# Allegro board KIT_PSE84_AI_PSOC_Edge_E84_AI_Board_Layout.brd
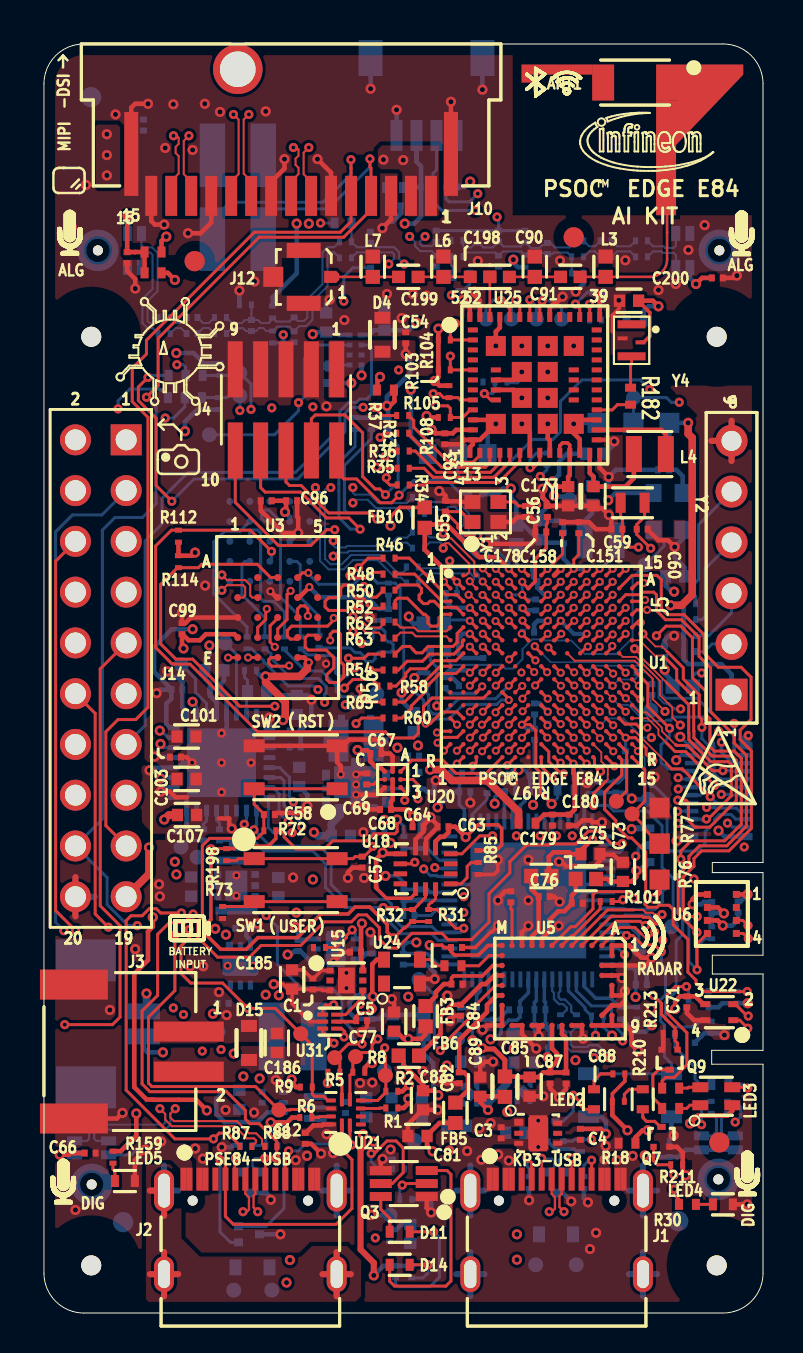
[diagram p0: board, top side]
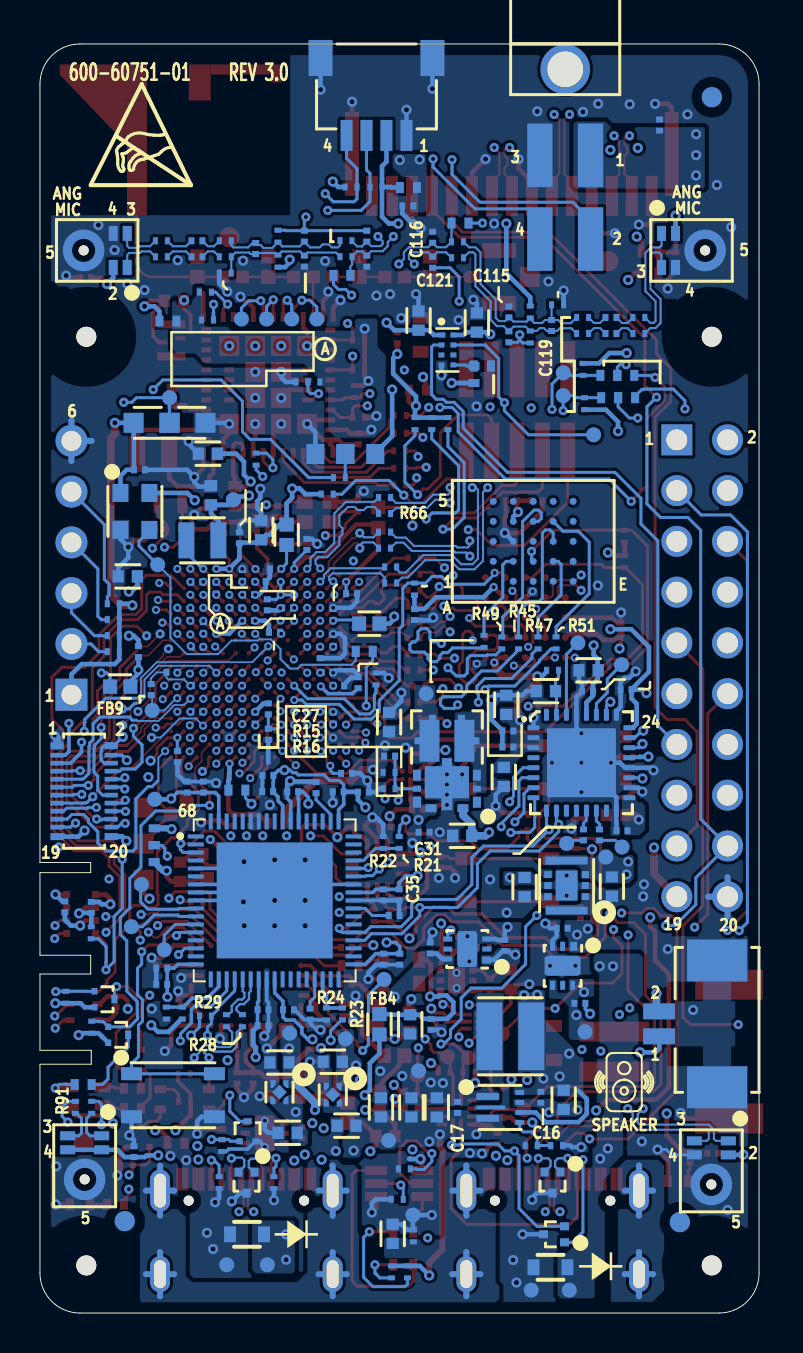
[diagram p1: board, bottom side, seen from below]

Outline 35.99 x 63.5 mm; copper layers: TOP, L02_GND, L03_SIG1, L04_SIG2, L05_PWR, BOTTOM. Coordinates in mm from the lower left corner of the outline.
Outline path: 0,61.5 arc(0.59,62.91) 2,63.5 33.99,63.5 arc(35.41,62.91) 35.99,61.5 35.99,22.54 33.45,22.54 33.45,22.03 35.99,22.03 35.99,17.9 33.45,17.9 33.45,16.96 35.99,16.96 35.99,13.14 33.43,13.14 33.43,12.45 35.99,12.45 35.99,2 arc(35.41,0.59) 33.99,0 2,0 arc(0.59,0.59) 0,2 0,61.5

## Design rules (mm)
constraint set DEFAULT: min track width 0.15
net group AMIC1_CTB_IN: nets AMIC1_CTB_INN AMIC1_CTB_INP
net group DP2: nets N17695662 N17695815
net group DP3: nets N17695725 N17695803
net group DP4: nets N17695749 N17695801
net group DP5: nets N17695747 N17695799
net group DP6: nets N17989965 N17989977
net group DP7: nets N17696044 N17696122
net group DP8: nets N17696068 N17696120
net group DP9: nets N17696066 N17696118
net group DP10: nets N17695981 N17696134
net group DP12: nets N17709188 N17709192
net group DP13: nets N17709220 N17709224
net group DP14: nets N17709256 N17709266
net group DSI_CLK: nets DSI_CLK_N DSI_CLK_P
net group DSI_DATA0: nets DSI_DATA0_N DSI_DATA0_P
net group DSI_DATA1: nets DSI_DATA1_N DSI_DATA1_P
net group KP_USB: nets N17581130 N17581131
net group P6_USB: nets PE84_USB_DM PE84_USB_DP
net group WL_SDIO_CMD: nets N17708163 WL_SDIO_CMD
net group WL_SDIO_DATA0: nets N17708293 WL_SDIO_DATA0
net group WL_SDIO_DATA1: nets N17708259 WL_SDIO_DATA1
net group WL_SDIO_DATA2: nets N17708201 WL_SDIO_DATA2
net group WL_SDIO_DATA3: nets N17708171 WL_SDIO_DATA3
net group I2S: nets I2S_TX_FSYNC I2S_TX_MCK I2S_TX_SCK I2S_TX_SD
net group POWER: nets AMIC_1V8 DISP_VDD_3V3 MCU_VDD_3V3 N17462113 N17691977 N17691999 N17694386 N17694402 N17699019 N17699478 N17701248 N17701356 N17701674 N17701786 N17713209 P5LP_VCCD P5LP_VDD PE84_VBUS PE84_VCCD PE84_VDDA USB_V_SENSE VBAT_IN VDD_5V VDDA_RADAR VDDD_RADAR VDDIO_RADIO VDDLF_RADAR VDDPLL_RADAR VDDRF_RADAR VDDVCO_RADAR VTARG_MEAS
net group RF: nets N17920449 N17920453 N17920674 N17920680 RF_OUT
net group SMIF0: nets N17708861 N17708893 N17708925 N17708957 N17709105
net group SMIF0_DATA: nets SMIF0_CLKP SMIF0_DATA0 SMIF0_DATA1 SMIF0_DATA2 SMIF0_DATA3
net group SMIF1: nets N17708863 N17708895 N17708927 N17708959 N17708991 N17709023 N17709055 N17709075 N17709107 N17709123 N17709155
net group SMIF1_DATA: nets SMIF1_CLKN SMIF1_CLKP SMIF1_DATA0 SMIF1_DATA1 SMIF1_DATA2 SMIF1_DATA3 SMIF1_DATA4 SMIF1_DATA5 SMIF1_DATA6 SMIF1_DATA7 SMIF1_RWDS

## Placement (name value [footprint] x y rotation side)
ANT1  2450AD18A6050  [ANTENNA_2450AD18A6050]  29.59 61.57 0 top
C1  0.1uF  [CAPC0603_0201N]  13.46 16.46 90 top
C3  0.1uF  [CAPC0603_0201N]  22.89 9.02 90 top
C4  0.1uF  [CAPC0603_0201N]  26.85 8.94 270 top
C5  0.1uF  [CAPC0603_0201N]  15.9 14.63 180 top
C6  0.1uF  [CAPC0603_0201N]  15.6 18.06 0 top
C7  0.1uF  [CAPC0603_0201N]  9.86 19.25 180 bottom
C8  0.1uF  [CAPC0603_0201N]  12.73 18.39 270 bottom
C9  0.1uF  [CAPC0603_0201N]  8.97 15.5 0 bottom
C11  0.1uF  [CAPC0603_0201N]  16.46 18.26 270 bottom
C12  0.1uF  [CAPC0603_0201N]  13.08 8.74 270 top
C13  10nF  [CAPC1005_0402N]  18.34 3.96 90 bottom
C14  22uF  [CAPC1005_0402N]  9.78 10.67 270 bottom
C16  0.1uF  [CAPC0603_0201N]  10.92 10.8 270 bottom
C17  0.1uF  [CAPC0603_0201N]  15.09 10.29 90 bottom
C21  10uF  [CAPC1005_0402N]  11.74 21.31 90 bottom
C27  330PF  [CAPC0603_0201N]  18.49 27.86 180 bottom
C28  22uF  [CAPC1005_0402N]  18.52 29.57 90 bottom
C30  10uF  [CAPC1005_0402N]  14.86 23.88 0 bottom
C31  1uF  [CAPC0603_0201N]  16.77 24.05 180 bottom
C35  1uF  [CAPC0603_0201N]  18.02 20.92 270 bottom
C36  0.1uF  [CAPC0603_0201N]  18.82 20.92 270 bottom
C37  1uF  [CAPC0603_0201N]  17.98 17.7 270 bottom
C38  0.1uF  [CAPC0603_0201N]  18.8 17.7 270 bottom
C39  1uF  [CAPC0603_0201N]  24.83 14.38 180 bottom
C40  0.1uF  [CAPC0603_0201N]  24.83 15.18 180 bottom
C41  1uF  [CAPC0603_0201N]  29.9 16.45 0 bottom
C42  0.1uF  [CAPC0603_0201N]  29.9 17.26 0 bottom
C43  1uF  [CAPC0603_0201N]  22.18 26.29 90 bottom
C44  1uF  [CAPC0603_0201N]  23.55 15.17 180 bottom
C45  0.1uF  [CAPC0603_0201N]  23.34 26.09 0 bottom
C46  1uF  [CAPC0603_0201N]  21.07 26.07 0 bottom
C47  0.1uF  [CAPC0603_0201N]  19.8 26.06 180 bottom
C48  1uF  [CAPC0603_0201N]  24.59 26.9 0 bottom
C49  0.1uF  [CAPC0603_0201N]  24.6 26.09 0 bottom
C50  1uF  [CAPC0603_0201N]  27.81 26.32 90 bottom
C51  0.1uF  [CAPC0603_0201N]  28.63 26.32 90 bottom
C52  1uF  [CAPC0603_0201N]  18.26 19.89 180 bottom
C53  1uF  [CAPC0603_0201N]  22.47 14.95 270 bottom
C54  1uF  [CAPC0603_0201N]  18.11 48.79 90 top
C55  10pF  [CAPC0603_0201N]  20.09 40.37 90 top
C56  10pF  [CAPC0603_0201N]  24.11 40.11 270 top
C57  0.1uF  [CAPC0603_0201N]  15.93 22.56 270 top
C58  0.1uF  [CAPC0603_0201N]  11.28 24.94 0 top
C59  22pF  [CAPC0603_0201N]  28.68 39.22 0 top
C60  22pF  [CAPC0603_0201N]  29.95 39.22 180 top
C61  0.1uF  [CAPC0603_0201N]  31.01 42.19 180 bottom
C62  0.1uF  [CAPC0603_0201N]  34.75 20.32 90 bottom
C63  0.1uF  [CAPC0603_0201N]  19.98 24.33 0 top
C64  0.1uF  [CAPC0603_0201N]  18.73 24.33 0 top
C65  0.1uF  [CAPC0603_0201N]  33.43 20.3 270 bottom
C66  0.1uF  [CAPC0603_0201N]  2.31 8 0 top
C67  0.1uF  [CAPC0603_0201N]  16.61 27.99 0 top
C68  0.1uF  [CAPC0603_0201N]  17.1 25.2 180 top
C69  2.2uF  [CAPC0603_0201N]  16.16 26.72 90 top
C70  0.1uF  [CAPC0603_0201N]  31.29 8.08 90 bottom
C71  0.1uF  [CAPC0603_0201N]  32.18 15.57 270 top
C72  0.47uF  [CAPC0603_0201N]  23.37 20.83 270 top
C73  10uF  [CAPC1005_0402N]  28.98 22.07 90 top
C74  1uF  [CAPC0603_0201N]  26.7 20.5 0 top
C75  10uF  [CAPC1005_0402N]  27.36 22.96 0 top
C76  1uF  [CAPC0603_0201N]  25.04 20.83 0 top
C77  10uF  [CAPC1005_0402N]  17.53 14.58 90 top
C78  1uF  [CAPC0603_0201N]  20.68 16.46 0 top
C79  10uF  [CAPC1005_0402N]  17.46 14.44 270 bottom
C80  1uF  [CAPC0603_0201N]  16.42 14.44 270 bottom
C81  10uF  [CAPC1005_0402N]  18.7 8.86 180 top
C82  1uF  [CAPC0603_0201N]  20.79 11.77 270 top
C83  10uF  [CAPC1005_0402N]  18.98 10.64 270 top
C84  1uF  [CAPC0603_0201N]  20.85 15.15 270 top
C85  10uF  [CAPC1005_0402N]  24.31 11.32 270 top
C86  1uF  [CAPC0603_0201N]  20.65 18.29 0 top
C87  1uF  [CAPC0603_0201N]  25.33 11.76 270 top
C88  1uF  [CAPC0603_0201N]  26.13 11.76 270 top
C89  10uF  [CAPC1005_0402N]  21.84 11.32 90 top
C90  8.2pF  [CAPC1005_0402M]  22.81 51.84 0 top
C91  2.7pF  [CAPC1005_0402M]  26.35 51.84 0 top
C92  4.7uF  [CAPC1005_0402N]  27.51 40.87 270 top
C93  0.1uF  [CAPC0603_0201N]  20.07 43.74 270 top
C94  4.7uF  [CAPC1005_0402N]  27.59 43 0 bottom
C95  4.7uF  [CAPC1005_0402N]  26.24 40.87 270 top
C96  1uF  [CAPC0603_0201N]  12.4 40.64 0 top
C97  0.1uF  [CAPC0603_0201N]  11.13 40.64 180 top
C98  1uF  [CAPC0603_0201N]  17.25 34.95 270 bottom
C99  0.1uF  [CAPC0603_0201N]  6.91 34.24 90 top
C100  0.033uF  [CAPC1005_0402N]  10.67 31.12 0 bottom
C101  22uF  [CAPC1005_0402N]  7.14 28.85 0 top
C102  0.1uF  [CAPC0603_0201N]  6.65 31.19 0 bottom
C103  22uF  [CAPC1005_0402N]  7.14 26.72 0 top
C104  0.1uF  [CAPC0603_0201N]  6.58 27.81 0 top
C105  0.47uF  [CAPC0603_0201N]  8.79 23.93 90 bottom
C106  0.47uF  [CAPC0603_0201N]  7.99 23.93 90 bottom
C107  10uF  [CAPC1005_0402N]  7.16 24.92 0 top
C108  0.1uF  [CAPC0603_0201N]  6.86 24.13 0 bottom
C109  10uF  [CAPC1005_0402N]  8.53 32.16 0 bottom
C110  0.1uF  [CAPC0603_0201N]  8.59 31.12 0 bottom
C111  10uF  [CAPC1005_0402N]  12.65 30.43 90 bottom
C112  0.1uF  [CAPC0603_0201N]  12.57 29.12 0 bottom
C113  10uF  [CAPC1005_0402N]  12.78 26.82 270 bottom
C114  0.1uF  [CAPC0603_0201N]  12.57 28.32 0 bottom
C115  10pF  [CAPC0603_0201N]  12.52 50.09 90 bottom
C116  12pF  [CAPC0603_0201N]  16.34 53.82 90 bottom
C117  0.1uF  [CAPC0603_0201N]  7.41 49.81 0 bottom
C118  0.1uF  [CAPC0603_0201N]  4.17 52.81 270 top
C119  390pF  [CAPC0603_0201N]  10.38 49.41 270 bottom
C120  0.1uF  [CAPC0603_0201N]  7.41 49.01 0 bottom
C121  12pF  [CAPC0603_0201N]  16.34 52.57 90 bottom
C122  10pF  [CAPC0603_0201N]  12.52 48.85 90 bottom
C123  10pF  [CAPC0603_0201N]  22.76 52.63 270 bottom
C124  12pF  [CAPC0603_0201N]  19.64 52.63 270 bottom
C125  0.1uF  [CAPC0603_0201N]  28.14 52.85 180 bottom
C126  0.1uF  [CAPC0603_0201N]  33.71 51.79 0 top
C127  390pF  [CAPC0603_0201N]  25.2 53.26 90 bottom
C128  0.1uF  [CAPC0603_0201N]  28.14 53.65 180 bottom
C129  12pF  [CAPC0603_0201N]  19.64 53.88 270 bottom
C130  10pF  [CAPC0603_0201N]  22.76 53.88 270 bottom
C136  1uF  [CAPC0603_0201N]  17.58 55.4 0 bottom
C137  1uF  [CAPC0603_0201N]  24.97 36.6 180 bottom
C138  0.1uF  [CAPC0603_0201N]  26.01 38.79 90 bottom
C139  10uF  [CAPC1005_0402N]  31.6 36.86 0 bottom
C140  0.1uF  [CAPC0603_0201N]  26.19 35.28 180 bottom
C141  0.1uF  [CAPC0603_0201N]  27.18 36.27 270 bottom
C142  0.1uF  [CAPC0603_0201N]  24.26 34.06 0 bottom
C143  0.1uF  [CAPC0603_0201N]  24.21 37.24 0 bottom
C144  0.1uF  [CAPC0603_0201N]  26.52 28.45 90 bottom
C145  0.1uF  [CAPC0603_0201N]  21.97 33.05 270 bottom
C146  0.1uF  [CAPC0603_0201N]  31.06 33.1 90 bottom
C147  1uF  [CAPC0603_0201N]  28.12 31.4 0 bottom
C148  1uF  [CAPC0603_0201N]  28.12 33.33 0 bottom
C149  0.1uF  [CAPC0603_0201N]  29.39 32.06 0 bottom
C150  4.7uF  [CAPC1005_0402N]  24.92 39.17 90 bottom
C151  0.1uF  [CAPC0603_0201N]  26.77 39.29 90 top
C152  4.7uF  [CAPC1005_0402N]  27.43 40.92 90 bottom
C153  1uF  [CAPC0603_0201N]  24.56 30.23 90 bottom
C154  0.1uF  [CAPC0603_0201N]  24.56 28.96 270 bottom
C155  1uF  [CAPC0603_0201N]  30.43 31.19 90 bottom
C156  1uF  [CAPC0603_0201N]  27.81 34.29 90 bottom
C157  1uF  [CAPC0603_0201N]  20.07 31.54 90 bottom
C158  1uF  [CAPC0603_0201N]  25.96 39.29 90 top
C159  1uF  [CAPC0603_0201N]  25.55 35.94 180 bottom
C160  1uF  [CAPC0603_0201N]  29.11 27.84 270 bottom
C161  1uF  [CAPC0603_0201N]  20.4 35.99 180 bottom
C162  1uF  [CAPC0603_0201N]  28.47 34.95 90 bottom
C163  1uF  [CAPC0603_0201N]  20.65 27 180 bottom
C164  1uF  [CAPC0603_0201N]  22.63 38.46 90 bottom
C165  0.1uF  [CAPC0603_0201N]  28.14 36.58 0 bottom
C166  0.1uF  [CAPC0603_0201N]  25.55 34.65 180 bottom
C167  0.1uF  [CAPC0603_0201N]  25.86 36.91 90 bottom
C168  0.1uF  [CAPC0603_0201N]  21.62 32.06 180 bottom
C169  0.1uF  [CAPC0603_0201N]  25.22 29.77 90 bottom
C170  0.1uF  [CAPC0603_0201N]  28.14 30.07 0 bottom
C171  1uF  [CAPC0603_0201N]  21.31 29.77 90 bottom
C172  1uF  [CAPC0603_0201N]  21.31 33.66 90 bottom
C173  1uF  [CAPC0603_0201N]  21.31 34.95 90 bottom
C174  1uF  [CAPC0603_0201N]  21.04 31.39 180 bottom
C175  0.1uF  [CAPC0603_0201N]  23.6 35.28 0 bottom
C176  0.1uF  [CAPC0603_0201N]  24.61 35.43 270 bottom
C177  1uF  [CAPC0603_0201N]  25.2 40.11 90 top
C178  1uF  [CAPC0603_0201N]  24.87 39.08 180 top
C179  1uF  [CAPC0603_0201N]  25.45 24.66 270 top
C180  0.1uF  [CAPC0603_0201N]  26.29 24.66 270 top
C182  22uF  [CAPC1005_0402N]  16.13 10.29 90 bottom
C183  22uF  [CAPC1005_0402N]  17.4 10.29 90 bottom
C184  22uF  [CAPC1005_0402N]  18.92 10.29 90 bottom
C185  22uF  [CAPC1005_0402N]  12.42 16.69 270 top
C186  22uF  [CAPC1005_0402N]  11.66 13.51 270 top
C189  1uF  [CAPC1005_0402N]  20.65 9.37 0 bottom
C191  1uF  [CAPC1005_0402N]  21.34 12.57 0 bottom
C194  1uF  [CAPC1005_0402N]  23.6 9.02 0 bottom
C196  1uF  [CAPC1005_0402N]  24 12.54 0 bottom
C197  10uF  [CAPC1005_0402N]  7.37 21.34 270 bottom
C198  8.2pF  [CAPC1005_0402M]  21.83 51.84 180 top
C199  8.2pF  [CAPC1005_0402M]  18.24 51.84 180 top
C200  1uF  [CAPC1005_0402N]  29.29 50.65 180 top
C203  1uF  [CAPC1005_0402N]  17.04 49.66 270 bottom
C204  1uF  [CAPC1005_0402N]  14.12 49.56 90 bottom
C205  1uF  [CAPC0603_0201N]  4.98 59.44 90 bottom
D1  T5V0S5A-7  [SODFL1608X77N]  25.63 3.94 180 bottom
D2  T5V0S5A-7  [SODFL1608X77N]  10.44 2.29 180 bottom
D4  ESD5V0D5-TP  [SODFL1608X77N]  16.94 48.95 270 top
D11  150040BS73220  [LEDC1005X35N_AMB_WURTH]  17.81 4.07 0 top
D14  150040RS73220  [LEDC1005X35N_AMB_WURTH]  17.81 2.41 0 top
D15  T5V0S5A-7  [SODFL1608X77N]  10.26 13.51 90 top
FB1  600 OHM  [INDC1005_0402M]  27.13 21.72 180 top
FB2  600 OHM  [INDC1005_0402M]  24.9 21.87 180 top
FB3  600 OHM  [INDC1005_0402M]  19.11 14.85 90 top
FB4  600 OHM  [INDC1005_0402M]  19 14.44 90 bottom
FB5  600 OHM  [INDC1005_0402M]  20.59 10.02 90 top
FB6  600 OHM  [INDC1005_0402M]  18.26 12.88 0 top
FB7  600 OHM  [INDC1005_0402M]  23.07 11.33 90 top
FB8  120 OHM  [INDC1005_0402M]  23.65 38.94 270 bottom
FB9  120 OHM  [INDC1005_0402M]  31.98 31.34 180 bottom
FB10  120 OHM  [INDC1005_0402M]  19.06 39.8 90 top
FB11  120 OHM  [INDC1005_0402M]  19.51 34.49 180 bottom
J1  629722000214  [GCT_USB4105-GF-A]  25.66 3.02 0 top
J2  629722000214  [GCT_USB4105-GF-A]  10.33 3.02 0 top
J3  620102131822  [JST_S2B-PH-SM4-TB-LF-SN]  3.8 13.08 90 top
J4  HDR 5x2  [SAMT_FTSH-105-XX-X-DV-K]  12.12 45.19 180 top
J5  PRPC006SFAN-RC  [SULLINS_PRPC006SFAN-RC]  34.42 30.94 90 top
J7  665104131822  [JST_SM04B-SRSS-TB]  19.15 61.37 0 bottom
J8  0532610271  [MOLEX_532610271]  5 13.84 270 bottom
J10  SFW15R-2STAE1LF  [AMPHENOL_SFW15R-2STAE1LF]  12.37 60.05 180 top
J12  A-1JB  [AMP_A-1JB_ALT1]  13 51.84 90 top
J14  CON 10x2  [RTST254P2X10_W515]  4.12 43.69 270 top
J16  TSM-102-01-L-DH-A-P-TR  [SAMTEC_TSM-102-01-L-DH-A-P-TR]  9.7 62.23 0 bottom
J17  DF40C-20DP-0.4V(51)  [HIROSE_DF40C-20DP-0P4V]  33.78 26.11 270 bottom
L1  1uH  [IND_74438336010]  12.45 13.84 0 bottom
L2  3nH  [INDC1005_0402M]  24.57 52.35 270 top
L3  3.6nH  [INDC1005_0402M]  28.11 52.35 270 top
L4  2.2uH  [IND_74479276222C]  30.33 42.98 0 top
L5  2.2uH  [IND_74479276222C]  27.87 38.66 180 bottom
L6  3nH  [INDC1005_0402M]  20 52.35 270 top
L7  3nH  [INDC1005_0402M]  16.46 52.35 270 top
LED1  150040GS73220  [LEDC1005X35N_AMB_WURTH]  29.97 10.69 90 top
LED2  150040BS73220  [LEDC1005X35N_AMB_WURTH]  27.53 10.69 90 top
LED3  150066M153000  [LED_150066M153000]  33.66 10.85 0 top
LED4  150040AS73220  [LEDC1005X35N_AMB_WURTH]  33.99 5.44 180 top
LED5  150040AS73220  [LEDC1005X35N_AMB_WURTH]  4.05 6.61 180 top
NOREF  -  []  31.66 13.3 0 top
NOREF#2  -  []  27.89 62.47 0 top
NOREF#3  -  []  9.28 18.35 0 top
NOREF#4  -  []  10.26 12.66 90 top
NOREF#5  -  []  13.58 17.29 0 top
NOREF#6  -  []  30.13 -0.66 90 top
NOREF#7  -  []  2.47 65 90 top
NOREF#8  -  []  -15.71 57.9 90 top
NOREF#9  -  []  6.97 60.96 90 top
NOREF#10  -  []  27.07 38.66 0 top
NOREF#11  -  []  31.25 11.65 0 top
NOREF#12  -  []  29.53 42.98 0 top
NOREF#13  -  []  21.19 6.69 0 top
NOREF#14  -  []  0 17.03 0 top
NOREF#15  -  []  14.36 9.43 90 top
NOREF#16  -  []  32.93 18.72 0 top
NOREF#17  -  []  3.07 57.9 90 top
NOREF#18  -  []  11.98 9.54 0 top
NOREF#19  -  []  33.11 15.45 0 top
NOREF#20  -  []  32.34 15.07 90 top
NOREF#21  -  []  16.94 48.1 90 top
NOREF#22  -  []  26.77 39.56 0 top
NOREF#23  -  []  14.91 10.68 0 top
NOREF#24  -  []  26.28 4.36 90 top
NOREF#25  -  []  15.63 17.29 90 top
NOREF#26  -  []  47.79 23.44 0 top
NOREF#27  -  []  33.06 14.3 90 top
NOREF#28  -  []  21.34 1.94 90 top
NOREF#29  -  []  10.33 16.4 90 top
NOREF#30  -  []  7.25 12.08 90 top
NOREF#31  -  []  5.37 55.9 0 top
NOREF#32  -  []  23.92 44.49 0 top
NOREF#33  -  []  11.4 13.84 0 top
NOREF#34  -  []  23.77 8.49 0 top
NOREF#35  -  []  11.09 2.71 90 top
NOREF#36  -  []  9.84 12.86 0 top
NOREF#37  -  []  27.99 61.57 0 top
NOREF#38  -  []  9.08 6.7 0 top
NOREF#39  -  []  1.5 9.73 90 top
NOREF#40  -  []  17.65 58.92 0 top
NOREF#41  -  []  31.43 42.08 90 top
NOREF#42  -  []  27.28 9.19 0 top
NOREF#43  -  []  32.21 13.52 0 top
NOREF#44  -  [unnamed#2]  2.37 2.38 0 top
NOREF#45  -  []  2.1 11.29 90 top
NOREF#46  -  []  17.17 25.21 90 top
NOREF#47  -  [unnamed#2]  33.68 2.38 0 top
NOREF#48  -  []  14.36 9.43 0 top
NOREF#49  -  []  32.91 8.87 0 top
NOREF#50  -  []  30.51 8.31 0 top
NOREF#51  -  []  51.23 29.52 90 top
NOREF#52  -  []  21.47 47.69 90 top
NOREF#53  -  []  2.39 6.43 90 top
NOREF#54  -  []  29.23 43.88 0 top
NOREF#55  -  []  4.37 58 0 top
NOREF#56  -  []  16.04 17.39 0 top
NOREF#57  -  [unnamed#2]  7.54 52.63 0 top
NOREF#58  -  []  14.36 9.83 90 top
NOREF#59  -  []  8.43 53.74 90 top
NOREF#60  -  []  18.31 2.16 90 top
NOREF#61  -  []  31.09 51.63 0 top
NOREF#62  -  []  8.58 6.7 0 top
NOREF#63  -  []  25.2 8.59 0 top
NOREF#64  -  []  0 9.13 90 top
NOREF#65  -  []  6.01 1.94 90 top
NOREF#66  -  []  1.5 9.73 90 top
NOREF#67  -  []  0.84 13.26 0 top
NOREF#68  -  []  16.31 3.31 90 top
NOREF#69  -  []  14.8 -0.66 90 top
NOREF#70  -  []  9.84 12.86 90 top
NOREF#71  -  []  34.42 38.56 90 top
NOREF#72  -  []  14.32 16.14 90 top
NOREF#73  -  []  14.01 9.24 90 top
NOREF#74  -  []  17.6 20.98 90 top
NOREF#75  -  []  17.37 55.9 0 top
NOREF#76  -  []  17.05 26.7 90 top
NOREF#77  -  []  13.43 10.29 90 top
NOREF#78  -  []  1.34 54.71 0 top
NOREF#79  -  []  30.22 11.19 0 top
NOREF#80  -  []  4.3 0 90 top
NOREF#81  -  []  54.13 -4.27 0 top
NOREF#82  -  []  31.54 8.39 90 top
NOREF#83  -  []  7.65 15.44 90 top
NOREF#84  -  []  17.37 49.6 90 top
NOREF#85  -  []  32.34 15.07 0 top
NOREF#86  -  []  15.31 9.38 90 top
NOREF#87  -  []  11.98 9.54 0 top
NOREF#88  -  []  13.63 17.66 90 top
NOREF#89  -  []  17.65 58.92 0 top
NOREF#90  -  []  15.53 26.06 0 top
NOREF#91  -  []  33.21 20.94 0 top
NOREF#92  -  []  8.58 22.69 0 top
NOREF#93  -  [unnamed#2]  33.81 8.54 0 top
NOREF#94  -  []  30.13 -0.66 90 top
NOREF#95  -  []  22.6 13.72 0 top
NOREF#96  -  []  17.84 21.48 0 top
NOREF#97  -  []  18.92 16.28 90 top
NOREF#98  -  []  14.36 10.63 0 top
NOREF#99  -  []  2.25 19.08 0 top
NOREF#100  -  []  4.2 11.04 90 top
NOREF#101  -  []  16.92 17.88 0 top
NOREF#102  -  []  24.41 6.7 0 top
NOREF#103  -  []  22.15 59.25 90 top
NOREF#104  -  []  24.82 49.84 0 top
NOREF#105  -  []  20.92 42.49 0 top
NOREF#106  -  []  -19.85 -36.06 0 top
NOREF#107  -  []  22.87 61.9 90 top
NOREF#108  -  [unnamed#2]  33.68 48.85 0 top
NOREF#109  -  []  3.24 7.91 90 top
NOREF#110  -  [unnamed#2]  2.37 48.85 0 top
NOREF#111  -  []  32.79 41.41 90 top
NOREF#112  -  []  17.6 20.98 0 top
NOREF#113  -  []  28.22 42.49 90 top
NOREF#114  -  []  25.43 4.36 0 top
NOREF#115  -  []  33.21 19.64 90 top
NOREF#116  -  []  14.29 10.86 0 top
NOREF#117  -  []  24.78 3.94 0 top
NOREF#118  -  []  1.17 19.14 90 top
NOREF#119  -  []  8.43 53.74 0 top
NOREF#120  -  []  31.66 13.3 90 top
NOREF#121  -  []  31.25 10.05 90 top
NOREF#122  -  []  17.37 49.6 0 top
NOREF#123  -  []  33.76 6.69 90 top
NOREF#124  -  []  0 11.04 0 top
NOREF#125  -  []  0.84 9.16 90 top
NOREF#126  -  []  23.77 8.99 90 top
NOREF#127  -  []  3.01 59.5 90 top
NOREF#128  -  []  10.97 57.93 90 top
NOREF#129  -  []  1.34 51.63 90 top
NOREF#130  -  []  10.68 20.09 90 top
NOREF#131  -  [unnamed#2]  26.52 53.82 0 top
NOREF#132  -  []  33.06 14.3 0 top
NOREF#133  -  []  18.6 21.21 0 top
NOREF#134  -  []  29.1 13.72 90 top
NOREF#135  -  []  0 2.61 0 top
NOREF#136  -  []  14.07 25.21 0 top
NOREF#137  -  []  17.02 16.48 0 top
NOREF#138  -  []  17.02 16.48 90 top
NOREF#139  -  []  30.92 13.18 0 top
NOREF#140  -  []  35.69 32.06 0 top
NOREF#141  -  []  30.19 41.41 0 top
NOREF#142  -  []  34.99 4.69 90 top
NOREF#143  -  []  30.32 39.38 90 top
NOREF#144  -  []  5 15.09 90 top
NOREF#145  -  []  10.24 2.71 0 top
NOREF#146  -  []  32.85 10.4 0 top
NOREF#147  -  []  16.35 62.8 0 top
NOREF#148  -  []  9.59 2.29 0 top
NOREF#149  -  []  5.98 17.44 90 top
NOREF#150  -  []  5 13.84 90 top
NOREF#151  -  []  32.76 23.25 0 top
NOREF#152  -  []  17.45 27.1 0 top
NOREF#153  -  []  21.34 1.94 0 top
NOREF#154  -  []  31.58 13.92 90 top
NOREF#155  -  []  17.65 58.92 90 top
NOREF#156  -  []  33.27 15.3 90 top
NOREF#157  -  []  23.91 6.7 0 top
NOREF#158  -  []  6.01 1.94 0 top
NOREF#159  -  []  32.58 13.52 90 top
NOREF#160  -  []  24.98 8.67 90 top
NOREF#161  -  []  35.14 27.11 90 top
NOREF#162  -  []  10.57 20.84 90 top
NOREF#163  -  []  11.91 11.34 0 top
NOREF#164  -  []  34.93 18.72 90 top
NOREF#165  -  []  34.51 14.65 90 top
NOREF#166  -  []  14.8 -0.66 90 top
NOREF#167  -  []  32.27 15.7 90 top
NOREF#168  -  []  1.54 8.61 0 top
NOREF#169  -  []  13.63 18.71 0 top
NOREF#170  -  []  35.17 51.63 90 top
NOREF#171  -  []  26 8.59 90 top
NOREF#172  -  []  17.31 2.66 0 top
NOREF#173  -  []  3.55 6.35 90 top
NOREF#174  -  []  32.85 10.4 90 top
NOREF#175  -  []  11.98 10.54 90 top
NOREF#176  -  []  3.55 6.35 0 top
NOREF#177  -  []  30.51 8.31 90 top
NOREF#178  -  []  8.91 16.35 0 top
NOREF#179  -  []  30.72 10.19 90 top
NOREF#180  -  []  27.28 9.19 90 top
NOREF#181  -  []  34.49 4.69 0 top
NOREF#182  -  []  15.53 26.06 90 top
NOREF#183  -  []  16.15 63.5 0 top
NOREF#184  -  []  27.43 18.39 0 top
NOREF#185  -  []  9.63 20.14 90 top
NOREF#186  -  []  8.69 20.84 0 top
NOREF#187  -  []  26.77 37.76 90 top
NOREF#188  -  []  35.14 23.84 90 top
NOREF#189  -  []  123.72 85.74 0 top
NOREF#190  -  []  14.32 16.14 0 top
NOREF#191  -  []  30.69 12.25 0 top
NOREF#192  -  []  32.21 9.42 90 top
NOREF#193  -  []  21.32 49.84 0 top
NOREF#194  -  []  23.72 9.92 0 top
NOREF#195  -  []  30.69 12.25 90 top
NOREF#196  -  []  34.61 8.17 90 top
NOREF#197  -  []  22.87 61.9 0 top
NOREF#198  -  []  22.93 16.39 90 top
NOREF#199  -  []  16.31 3.31 0 top
NOREF#200  -  []  30.29 9.24 0 top
NOREF#201  -  []  30.32 39.38 0 top
NOREF#202  -  []  65.69 270.95 0 top
NOREF#203  -  []  31.29 60.67 90 top
NOREF#204  -  []  -17.33 65 0 top
NOREF#205  -  []  31.32 12.18 90 top
NOREF#206  -  []  14.29 9.21 90 top
NOREF#207  -  []  32.76 23.25 90 top
NOREF#208  -  []  16.04 15.89 90 top
NOREF#209  -  []  24.98 9.52 0 top
NOREF#210  -  []  6.97 63.5 90 top
NOREF#211  -  []  44 40.64 0 top
NOREF#212  -  []  25.77 8.07 90 top
NOREF#213  -  []  5.86 6.69 0 top
NOREF#214  -  []  21.32 43.04 90 top
NOREF#215  -  []  21.47 43.69 90 top
NOREF#216  -  []  8.91 16.35 90 top
NOREF#217  -  []  21.47 49.19 0 top
NOREF#218  -  []  7.65 18.64 0 top
NOREF#219  -  [unnamed#2]  3.96 4.55 180 bottom
NOREF#220  -  [unnamed#2]  2.36 60.83 180 bottom
NOREF#221  -  [unnamed#2]  31.75 4.6 180 bottom
Q3  BSD840NH6327XTSA1  [SOT65P210X100-6M]  18.01 6.48 180 top
Q7  XP222N03017R-G  [SOTFL40P120X50-3N_MOSFET_TOREX]  30.91 8.81 0 top
Q8  XP222N03017R-G  [SOTFL40P120X50-3N_MOSFET_TOREX]  25.6 9.09 180 bottom
Q9  XP222N03017R-G  [SOTFL40P120X50-3N_MOSFET_TOREX]  31.32 12.68 180 top
Q10  XP222N03017R-G  [SOTFL40P120X50-3N_MOSFET_TOREX]  32.77 15.7 270 bottom
Q11  XP222N03017R-G  [SOTFL40P120X50-3N_MOSFET_TOREX]  32.08 13.92 270 bottom
R1  887K  [RESC0603_0201N]  17.41 10.26 0 top
R2  100K  [RESC0603_0201N]  17.41 11.09 180 top
R3  5.1K  [RESC0603_0201N]  27.03 6.52 270 bottom
R4  5.1K  [RESC0603_0201N]  24.28 6.52 270 bottom
R5  100K  [RESC0603_0201N]  14.51 12.05 180 top
R6  100K  [RESC0603_0201N]  13.11 9.78 0 top
R7  100K  [RESC0603_0201N]  17.3 3.86 90 bottom
R8  100K  [RESC0603_0201N]  15.76 12.05 0 top
R9  100K  [RESC0603_0201N]  13.13 11.3 0 top
R10  348K  [RESC0603_0201N]  11.41 8.38 180 bottom
R11  47K  [RESC0603_0201N]  10.14 8.38 180 bottom
R15  47K  [RESC0603_0201N]  18.52 27.05 180 bottom
R16  15K  [RESC0603_0201N]  18.52 26.23 0 bottom
R18  0 OHM  [RESC1005_0402N]  29.18 8.5 180 top
R21  49.9K  [RESC0603_0201N]  18.01 23.55 270 bottom
R22  49.9K  [RESC0603_0201N]  18.81 23.55 270 bottom
R23  15K  [RESC0603_0201N]  20.85 14.96 90 bottom
R24  30K  [RESC0603_0201N]  21.65 14.96 90 bottom
R25  15K  [RESC0603_0201N]  28.87 15.01 90 bottom
R26  22 OHM  [RESC0603_0201N]  26.66 14.63 90 bottom
R27  30K  [RESC0603_0201N]  29.67 15.01 90 bottom
R28  22 OHM  [RESC0603_0201N]  25.86 14.63 90 bottom
R29  4.7K  [RESC0603_0201N]  27.71 14.86 0 bottom
R30  560 OHM  [RESC1005_0402N]  32.21 5.44 180 top
R31  2.2K  [RESC0603_0201N]  19.25 19.89 270 top
R32  2.2K  [RESC0603_0201N]  18.45 19.89 270 top
R33  33 OHM  [RESC0603_0201N]  17.96 44.02 0 top
R34  33 OHM  [RESC0603_0201N]  17.98 41.43 0 top
R35  33 OHM  [RESC0603_0201N]  17.98 42.27 0 top
R36  33 OHM  [RESC0603_0201N]  17.98 43.13 0 top
R37  33 OHM  [RESC0603_0201N]  17.96 44.91 0 top
R38  33 OHM  [RESC0603_0201N]  25.17 42.72 90 bottom
R45  33 OHM  [RESC0603_0201N]  12.04 33.53 270 bottom
R46  33 OHM  [RESC0603_0201N]  17.27 37.77 180 top
R47  33 OHM  [RESC0603_0201N]  11.06 33.53 270 bottom
R48  33 OHM  [RESC0603_0201N]  17.27 36.97 180 top
R49  33 OHM  [RESC0603_0201N]  12.88 33.53 270 bottom
R50  33 OHM  [RESC0603_0201N]  17.27 36.17 180 top
R51  33 OHM  [RESC0603_0201N]  10.16 33.53 270 bottom
R52  33 OHM  [RESC0603_0201N]  17.27 35.37 180 top
R54  33 OHM  [RESC0603_0201N]  17.27 32.17 180 top
R56  33 OHM  [RESC0603_0201N]  17.27 32.97 180 top
R58  33 OHM  [RESC0603_0201N]  17.02 31.37 180 top
R60  33 OHM  [RESC0603_0201N]  17.27 29.77 180 top
R61  33 OHM  [RESC0603_0201N]  13.77 33.61 270 bottom
R62  33 OHM  [RESC0603_0201N]  17.27 34.57 180 top
R63  33 OHM  [RESC0603_0201N]  17.27 33.77 180 top
R65  33 OHM  [RESC0603_0201N]  17.27 30.57 180 top
R66  33 OHM  [RESC0603_0201N]  18.75 40.01 0 bottom
R67  33 OHM  [RESC0603_0201N]  18.75 40.81 0 bottom
R68  33 OHM  [RESC0603_0201N]  18.75 39.07 0 bottom
R69  33 OHM  [RESC0603_0201N]  18.75 38.27 0 bottom
R70  33 OHM  [RESC0603_0201N]  18.44 37.33 0 bottom
R71  33 OHM  [RESC0603_0201N]  18.44 36.53 0 bottom
R72  4.7K  [RESC0603_0201N]  11.31 24.13 180 top
R73  1K  [RESC0603_0201N]  8.94 20.04 90 top
R76  4.7K  [RESC1608_0603M]  30.81 22.59 90 top
R77  4.7K  [RESC1608_0603M]  30.81 24.39 90 top
R79  4.7K  [RESC1608_0603M]  30.41 44.54 180 bottom
R80  4.7K  [RESC1608_0603M]  28.61 44.54 180 bottom
R84  100K  [RESC0603_0201N]  33.43 19.03 90 bottom
R85  0 OHM  [RESC0603_0201N]  21.73 22.84 90 top
R86  0 OHM  [RESC0603_0201N]  21.73 22.24 270 top
R87  100 OHM  [RESC0603_0201N]  10.1 8.33 180 top
R88  0 OHM  [RESC0603_0201N]  11.36 8.33 0 top
R91  100 OHM  [RESC0603_0201N]  33.4 10.29 90 bottom
R92  0 OHM  [RESC0603_0201N]  34.22 10.29 90 bottom
R101  0 OHM  [RESC0603_0201N]  28.14 20.59 180 top
R102  150 OHM  [RESC1005_0402N]  20.47 17.37 0 top
R103  10K  [RESC0603_0201N]  20.04 47.19 0 top
R104  10K  [RESC0603_0201N]  20.04 48.69 0 top
R105  10K  [RESC0603_0201N]  20.27 46.1 270 top
R106  10K  [RESC0603_0201N]  27.61 49.68 180 bottom
R107  10K  [RESC0603_0201N]  27.71 51.08 180 bottom
R108  10K  [RESC0603_0201N]  20.04 44.81 0 top
R109  10K  [RESC0603_0201N]  22.28 46.58 0 bottom
R110  0 OHM  [RESC0603_0201N]  22.88 46.58 180 bottom
R112  10K  [RESC0603_0201N]  6.73 38.87 270 top
R114  10K  [RESC0603_0201N]  6.73 37.59 90 top
R123  10K  [RESC0603_0201N]  10.34 32.16 0 bottom
R124  0 OHM  [RESC1005_0402N]  5.46 53.09 180 top
R125  2.55M  [RESC0603_0201N]  11.45 50.09 270 bottom
R126  2.55M  [RESC0603_0201N]  10.08 50.45 0 bottom
R127  40.2K  [RESC0603_0201N]  8.83 49.81 0 bottom
R128  40.2K  [RESC0603_0201N]  15.09 53.6 0 bottom
R129  0 OHM  [RESC0603_0201N]  6.01 49.81 0 bottom
R130  0 OHM  [RESC0603_0201N]  6.01 49.01 0 bottom
R131  40.2K  [RESC0603_0201N]  8.83 49.01 0 bottom
R132  40.2K  [RESC0603_0201N]  15.09 52.8 0 bottom
R133  1.27M  [RESC0603_0201N]  11.45 48.84 270 bottom
R134  2.55M  [RESC0603_0201N]  24.08 52.63 90 bottom
R135  2.55M  [RESC0603_0201N]  26.72 52.03 180 bottom
R136  40.2K  [RESC0603_0201N]  26.72 52.85 180 bottom
R137  40.2K  [RESC0603_0201N]  20.68 52.85 180 bottom
R138  0 OHM  [RESC0603_0201N]  29.92 52.85 180 bottom
R139  0 OHM  [RESC0603_0201N]  29.92 53.65 180 bottom
R140  40.2K  [RESC0603_0201N]  26.72 53.65 180 bottom
R141  40.2K  [RESC0603_0201N]  20.68 53.65 180 bottom
R142  1.27M  [RESC0603_0201N]  24.08 53.88 90 bottom
R153  0 OHM  [RESC1005_0402N]  17.55 56.31 0 bottom
R154  0 OHM  [RESC1005_0402N]  26.14 26.16 0 bottom
R155  200OHM  [RESC0603_0201N]  19.18 31.73 90 bottom
R156  470 OHM  [RESC1005_0402N]  31.37 10.24 0 top
R157  560 OHM  [RESC1005_0402N]  31.37 11.25 0 top
R159  100 OHM  [RESC0603_0201N]  3.45 7.8 90 top
R165  150 OHM  [RESC1005_0402N]  33.83 11.43 180 bottom
R173  100K  [RESC0603_0201N]  18.11 5.69 180 bottom
R174  1K  [RESC0603_0201N]  17.6 2.06 90 bottom
R182  0 OHM  [RESC1005_0402N]  29.36 45.87 270 top
R187  0 OHM  [RESC1608_0603N]  21.46 42.98 180 bottom
R188  0 OHM  [RESC1608_0603N]  19.96 42.98 180 bottom
R189  10K  [RESC0603_0201N]  21.01 41.8 180 bottom
R190  1K  [RESC0603_0201N]  18.4 2.06 90 bottom
R191  100K  [RESC0603_0201N]  17.76 7.21 180 bottom
R192  100K  [RESC0603_0201N]  32.32 35.49 180 bottom
R193  100K  [RESC0603_0201N]  32.32 34.69 180 bottom
R194  100K  [RESC0603_0201N]  32.32 33.89 180 bottom
R195  100K  [RESC0603_0201N]  32.32 33.09 180 bottom
R196  0 OHM  [RESC1005_0402N]  17.09 46.18 180 top
R197  0 OHM  [RESC1005_0402N]  24.18 24.51 180 top
R198  4.7K  [RESC0603_0201N]  9.15 22.94 270 top
R199  10K  [RESC0603_0201N]  21.62 40.97 180 bottom
R200  10K  [RESC0603_0201N]  17.22 44.5 270 bottom
R201  10K  [RESC0603_0201N]  16.38 44.5 270 bottom
R202  10K  [RESC0603_0201N]  15.57 44.5 270 bottom
R203  0 OHM  [RESC1005_0402N]  29.59 49.63 0 bottom
R204  4.7K  [RESC0603_0201N]  8.81 47.21 270 bottom
R205  4.7K  [RESC0603_0201N]  8.74 45.5 90 bottom
R206  4.7K  [RESC0603_0201N]  19.17 56.34 180 bottom
R207  4.7K  [RESC0603_0201N]  20.42 56.34 0 bottom
R208  10K  [RESC0603_0201N]  17.25 36.22 270 bottom
R209  2.2K  [RESC0603_0201N]  28.75 10.59 180 top
R210  1K  [RESC0603_0201N]  28.78 11.96 0 top
R211  100K  [RESC0603_0201N]  31.67 7.42 180 top
R212  100K  [RESC0603_0201N]  26.9 8.38 90 bottom
R213  100K  [RESC0603_0201N]  31.29 14 0 top
R214  100K  [RESC0603_0201N]  34.7 15.8 90 bottom
R215  100K  [RESC0603_0201N]  33.4 14.3 90 bottom
R216  0 OHM  [RESC1005_0402N]  13.84 47.38 180 bottom
R217  0 OHM  [RESC1005_0402N]  14.27 46.96 270 bottom
R218  0 OHM  [RESC1005_0402N]  19.76 33.1 180 bottom
R219  10K  [RESC0603_0201N]  13.79 18.29 180 top
R220  0 OHM  [RESC1005_0402N]  6.67 46.91 180 bottom
R221  0 OHM  [RESC1005_0402N]  7.52 46.91 0 bottom
R222  0 OHM  [RESC1005_0402N]  7.48 45.8 0 bottom
R223  0 OHM  [RESC1005_0402N]  6.63 45.8 180 bottom
R224  0 OHM  [RESC1005_0402N]  5.46 52.05 180 top
R225  0 OHM  [RESC1005_0402N]  30.28 22.99 90 bottom
R226  0 OHM  [RESC1005_0402N]  30.28 23.83 270 bottom
R227  0 OHM  [RESC1005_0402N]  14.97 54.53 0 bottom
R228  0 OHM  [RESC1005_0402N]  20.88 51.92 180 bottom
SW1  434123025826  [SW_SKRPACE010]  12.6 21.66 0 top
SW2  434133025816  [SW_434133025816]  12.6 27.31 180 top
SW3  434123025826  [SW_SKRPACE010]  29.34 10.9 180 bottom
TP1  TP_SMD  [ICT_TP_SMD_030RD_NSP]  24.61 2.41 180 bottom
TP2  TP_SMD  [ICT_TP_SMD_030RD_NSP]  26.65 2.41 180 bottom
TP3  TP_SMD  [ICT_TP_SMD_030RD_NSP]  17.09 11.89 180 top
TP4  TP_SMD  [ICT_TP_SMD_030RD_NSP]  14.55 12.78 180 top
TP5  TP_SMD  [ICT_TP_SMD_030RD_NSP]  11.76 10.16 180 top
TP6  TP_SMD  [ICT_TP_SMD_030RD_NSP]  15.6 12.83 180 top
TP7  TP_SMD  [ICT_TP_SMD_030RD_NSP]  12.85 13.97 180 top
TP8  TP_SMD  [ICT_TP_SMD_030RD_NSP]  8.71 14.07 180 bottom
TP9  TP_SMD  [ICT_TP_SMD_030RD_NSP]  9.5 1.14 180 bottom
TP10  TP_SMD  [ICT_TP_SMD_030RD_NSP]  11.41 1.14 180 bottom
TP12  TP_SMD  [ICT_TP_SMD_030RD_NSP]  18.54 8.64 180 bottom
TP16  TP_SMD  [ICT_TP_SMD_030RD_NSP]  30.25 25.71 180 bottom
TP17  TP_SMD  [ICT_TP_SMD_030RD_NSP]  17.32 4.9 180 bottom
TP18  TP_SMD  [ICT_TP_SMD_030RD_NSP]  30.91 21.44 180 bottom
TP19  TP_SMD  [ICT_TP_SMD_030RD_NSP]  29.78 18.18 180 bottom
TP20  TP_SMD  [ICT_TP_SMD_030RD_NSP]  31.42 19.33 180 bottom
TP21  TP_SMD  [ICT_TP_SMD_030RD_NSP]  18.77 16.69 180 bottom
TP22  TP_SMD  [ICT_TP_SMD_030RD_NSP]  6.88 32.44 180 bottom
TP23  TP_SMD  [ICT_TP_SMD_030RD_NSP]  9.07 33.53 180 bottom
TP24  TP_SMD  [ICT_TP_SMD_030RD_NSP]  9.63 23.5 180 bottom
TP25  TP_SMD  [ICT_TP_SMD_030RD_NSP]  6.86 23.32 180 bottom
TP45  TP_SMD  [ICT_TP_SMD_030RD_NSP]  26.31 40.69 270 bottom
TP46  TP_SMD  [ICT_TP_SMD_030RD_NSP]  30.38 30.15 0 bottom
TP47  TP_SMD  [ICT_TP_SMD_030RD_NSP]  17.04 12.12 180 bottom
TP48  TP_SMD  [ICT_TP_SMD_030RD_NSP]  16.66 30.99 90 bottom
TP49  TP_SMD  [ICT_TP_SMD_030RD_NSP]  7.67 22.81 270 bottom
TP50  TP_SMD  [ICT_TP_SMD_030RD_NSP]  23.5 14 0 bottom
TP51  TP_SMD  [ICT_TP_SMD_030RD_NSP]  20.7 13.72 180 bottom
TP52  TP_SMD  [ICT_TP_SMD_030RD_NSP]  30.1 37.44 180 bottom
TP53  TP_SMD  [ICT_TP_SMD_030RD_NSP]  25.91 49.73 180 bottom
TP54  TP_SMD  [ICT_TP_SMD_030RD_NSP]  24.65 49.73 180 bottom
TP55  TP_SMD  [ICT_TP_SMD_030RD_NSP]  22.14 49.73 180 bottom
TP56  TP_SMD  [ICT_TP_SMD_030RD_NSP]  23.39 49.73 180 bottom
TP65  TP_SMD  [ICT_TP_SMD_030RD_NSP]  29.51 45.8 180 bottom
TP66  TP_SMD  [ICT_TP_SMD_030RD_NSP]  29.44 24.97 0 top
TP69  TP_SMD  [ICT_TP_SMD_030RD_NSP]  28.65 25.6 0 top
TP70  TP_SMD  [ICT_TP_SMD_030RD_NSP]  8.28 43.94 180 bottom
TP71  TP_SMD  [ICT_TP_SMD_030RD_NSP]  9.8 45.9 180 bottom
TP72  TP_SMD  [ICT_TP_SMD_030RD_NSP]  9.8 47.04 180 bottom
U1  PSE846GPS2DBZC4  [BGA220C65P15X15_1000X1000X100_EXPLORER]  24.89 32.36 0 top
U2  CY8C5868LTI-LP039  [QFN40P800X800_68-H580N]  24.25 20.64 180 bottom
U3  S70KS1283GABHI020  [BGA24C100P5X5_600X800X120]  11.7 34.8 0 top
U4  S25HS512TFABHI013  [BGA24C100P5X5_600X800X120]  11.3 38.61 90 bottom
U5  BGT60TR13CE6327XUMA1  [VF2BGA40N50P9X12_500X650X90]  25.85 16.22 270 top
U6  DPS368XTSA1  [LGA8S145X65P2X4_200X250X110]  33.93 19.97 270 top
U7  IM73D122V01XTMA1  [MIC_IM73D122V01]  33.76 7.37 0 bottom
U8  IM73D122V01XTMA1  [MIC_IM73D122V01]  2.39 7.11 0 bottom
U9  IM73A135V01XTSA1  [MIC_IM73A135V01XTSA1]  33.13 53.17 90 bottom
U10  IM73A135V01XTSA1  [MIC_IM73A135V01XTSA1]  3.38 53.17 270 bottom
U13  XCL212B082DR  [CONV_XCL212B082DR]  15.62 27.56 0 bottom
U15  XC8111AA018R-G  [XFDFN50P180X150X33-7N_TOREX]  15.14 16.64 0 top
U18  BMI270  [BOSCH_BMI323]  19.1 22.23 180 top
U19  ESD7L5.0DT5G  [SOTFL40P120X59-3N]  25.65 6.52 270 bottom
U20  BMM350  [BOSCH_BMM350]  17.45 26.7 270 top
U21  TUSB321RWBR  [X2QFN40P160X160X40-12N_TI]  15.11 10.03 90 top
U22  SHT40-AD1B-R2  [SENSOR_SHT40-AD1B-R2]  33.81 15.05 180 top
U23  XC8114AA016R-G  [SON50P200X180X60-6N_TP]  9.83 17.37 270 bottom
U24  80 MHz  [OSCCC200X160X80-4N]  17.92 17.08 0 top
U25  LBEE5HY2FY  [MODULE_LBEE5HY2FY]  24.57 46.44 270 top
U26  XC8114AA016R-G  [SON50P200X180X60-6N_TP]  14.61 18.21 0 bottom
U27  XC8114AA016R-G  [SON50P200X180X60-6N_TP]  24.74 8.99 0 top
U28  TLV320DAC3100  [QFN50P500X500X100-32N_TP_NOFID]  8.89 27.53 180 bottom
U29  TPS61022RWUR  [VQFN50P200X200X100-7N_TI]  12.96 10.29 180 bottom
U30  ESD7L5.0DT5G  [SOTFL40P120X59-3N]  10.34 6.53 270 bottom
U31  74LVC2G14GS,132  [DFN35P100X100X40-6N]  14.3 14.58 0 top
U33  NCP163AMX180TBG  [DFN65P100X100X43-5N]  24 11.05 0 bottom
U34  XCL240B183FR-G  [CONV_XCL240B183FR-G]  9.63 21.39 90 bottom
U35  NCP163AMX330TBG  [DFN65P100X100X43-5N]  21.34 10.92 0 bottom
U36  ESD7L5.0DT5G  [SOTFL40P120X59-3N]  10.26 3.94 0 bottom
U40  74LVCH2T45GT,115  [SON50P100X200_08_SOT833-1]  15.6 48.18 180 bottom
Y1  17.2032MHz  [XTALS4_2MX1M6]  22.1 40.08 90 top
Y2  32.768kHz  [XTAL_ABS05_1M6X1M]  29.47 40.54 180 top
Y3  24MHZ  [OSCCC200X250X90-4N]  31.24 40.11 270 bottom
Y4  SIT1533AI-H4-DCC-32.768E  [OSCS4_SIT_2M0X1M2SPL_NGOPQ]  29.41 48.67 0 top

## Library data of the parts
ANT1 = ANT_RFANT3216120A5T
C1 C3-C9 C11-C14 C16 C17 C21 C27 C28 C30 C31 C35-C130 C136-C180 C182-C186 C189 C191 C194 C196-C200 C203-C205 = CAP-NP
D1 D2 D4 D15 = DIO-TVS
D11 D14 LED1 LED2 LED4 LED5 = DIO-LED
FB1-FB11 = FB
J1 J2 = USB_TYPE_C-16PIN_4SH
J3 J8 = PLG-2-J_SH1_2
J4 = PLG-10-ODD-EVEN-J
J5 = PLG-6-J
J7 = PLG-4-2SH-J
J10 = SKT-15-2SH-J
J12 = A-1JB
J14 = SKT-20-ODD-EVEN-J: User Part Number: Part No
J16 = PLG-4-ODD-EVEN-J
J17 = PLG-20-ODD-EVEN-4SH-J
L1 = IND-SHIELDED
L2-L7 = IND
LED3 = LED_150066M153000
Q3 = FET-MOS-N-G2S1D6-5G4S3D
Q7-Q11 = FET-MOS-N_XP222N03017R
R1-R11 R15 R16 R18 R21-R32 R38 R66-R73 R76 R77 R79 R80 R84-R88 R91 R92 R101-R110 R112 R114 R123-R142 R153-R157 R159 R165 R173 R174 R182 R187-R228 = RES
R33-R37 R45-R52 R54 R56 R58 R60-R63 R65 = RES: signal model: RES_RESC0603_0201N_DISCRETE_33_OHM_33_OHM
SW1-SW3 = SWITCH-PB-12-34
TP1-TP10 TP12 TP16-TP25 TP45-TP56 TP65 TP66 TP69-TP72 = TP_SMD: User Part Number: Part No
U1 = Explorer_220BGA_rev9280_May22
U2 = CY8C5868LTI-LP039
U3 = IC_S70KS1283GAB
U4 = IC_S25HS512TFABHI013
U5 = IC_BGT60TR13C
U6 = IC_DPS368
U7 U8 = IC_IM73D122V01
U9 U10 = IM73A135V01XTSA1
U13 = IC_XCL212B082DR_0
U15 = IC_XC8111AA018R-G
U18 = IC_BMI270
U19 U30 U36 = ESD-ESD7L_SESD7L
U20 = IC_BMM350
U21 = IC_TUSB321_0
U22 = IC_SHT40-AD1B-R2
U23 U26 U27 = IC_XC8114AA016R-G
U24 = OSC-KC2016K
U25 = MOD_LBEE5HY2FY
U28 = TLV320DAC3100
U29 = IC_TPS61022_0
U31 = IC_74LVC2G14GS
U33 U35 = NCP163AMX150TBG
U34 = IC_XCL240B183FR-G_0
U40 = 74LVCH2T45GT: User Part Number: Part No
Y1 = XTAL-4P-2G4G
Y2 = XTAL-2P
Y3 = ECS-2520MV
Y4 = OSC-SiT1533: User Part Number: Part No

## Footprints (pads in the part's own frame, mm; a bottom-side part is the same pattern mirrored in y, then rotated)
AMP_A-1JB_ALT1
  rect 0.75x1.7 smd: G1(-1.325,0) G3(1.325,0)
  rect 1x1 smd: G2(0,1.524)
  custom 0.15x0.15 smd: S(0,-1.399)
AMPHENOL_SFW15R-2STAE1LF
  rect 0.6x2 smd: 1(-7,4.15) 2(-6,4.15) 3(-5,4.15) 4(-4,4.15) 5(-3,4.15) 6(-2,4.15) 7(-1,4.15) 8(0,4.15) 9(1,4.15) 10(2,4.15) 11(3,4.15) 12(4,4.15) 13(5,4.15) 14(6,4.15) 15(7,4.15)
  rect 0.7x4.2 smd: SH1(-8,2.05) SH2(8,2.05)
ANTENNA_2450AD18A6050
  rect 1.1x1.8 smd: 1(1.6,0) 2(-1.6,0)
BGA24C100P5X5_600X800X120
  round 0.35 smd: A2(-1,2) A3(0,2) A4(1,2) A5(2,2) B1(-2,1) B2(-1,1) B3(0,1) B4(1,1) B5(2,1) C1(-2,0) C2(-1,0) C3(0,0) C4(1,0) C5(2,0) D1(-2,-1) D2(-1,-1) D3(0,-1) D4(1,-1) D5(2,-1) E1(-2,-2) E2(-1,-2) E3(0,-2) E4(1,-2) E5(2,-2)
BGA220C65P15X15_1000X1000X100_EXPLORER
  round 0.22 smd: A2(-3.9,4.55) A3(-3.25,4.55) A4(-2.6,4.55) A5(-1.95,4.55) A6(-1.3,4.55) A7(-0.65,4.55) A8(0,4.55) A9(0.65,4.55) A10(1.3,4.55) A11(1.95,4.55) A12(2.6,4.55) A13(3.25,4.55) A14(3.9,4.55) B1(-4.55,3.9) B2(-3.9,3.9) B3(-3.25,3.9) B4(-2.6,3.9) B5(-1.95,3.9) B6(-1.3,3.9) B7(-0.65,3.9) B8(0,3.9) B9(0.65,3.9) B10(1.3,3.9) B11(1.95,3.9) B12(2.6,3.9) B13(3.25,3.9) B14(3.9,3.9) B15(4.55,3.9) C1(-4.55,3.25) C2(-3.9,3.25) C3(-3.25,3.25) C4(-2.6,3.25) C5(-1.95,3.25) C6(-1.3,3.25) C7(-0.65,3.25) C8(0,3.25) C9(0.65,3.25) C10(1.3,3.25) C11(1.95,3.25) C12(2.6,3.25) C13(3.25,3.25) C14(3.9,3.25) C15(4.55,3.25) D1(-4.55,2.6) D2(-3.9,2.6) D3(-3.25,2.6) D4(-2.6,2.6) D5(-1.95,2.6) D6(-1.3,2.6) D7(-0.65,2.6) D8(0,2.6) D9(0.65,2.6) D10(1.3,2.6) D11(1.95,2.6) D12(2.6,2.6) D13(3.25,2.6) D14(3.9,2.6) D15(4.55,2.6) E1(-4.55,1.95) E2(-3.9,1.95) E3(-3.25,1.95) E4(-2.6,1.95) E5(-1.95,1.95) E6(-1.3,1.95) E7(-0.65,1.95) E8(0,1.95) E9(0.65,1.95) E10(1.3,1.95) E11(1.95,1.95) E12(2.6,1.95) E13(3.25,1.95) E14(3.9,1.95) E15(4.55,1.95) F1(-4.55,1.3) F2(-3.9,1.3) F3(-3.25,1.3) F4(-2.6,1.3) F5(-1.95,1.3) F6(-1.3,1.3) F7(-0.65,1.3) F8(0,1.3) F9(0.65,1.3) F10(1.3,1.3) F11(1.95,1.3) F12(2.6,1.3) F13(3.25,1.3) F14(3.9,1.3) F15(4.55,1.3) G2(-3.9,0.65) G3(-3.25,0.65) G4(-2.6,0.65) G5(-1.95,0.65) G6(-1.3,0.65) G7(-0.65,0.65) G8(0,0.65) G9(0.65,0.65) G10(1.3,0.65) G11(1.95,0.65) G12(2.6,0.65) G13(3.25,0.65) G14(3.9,0.65) H1(-4.55,0) H2(-3.9,0) H3(-3.25,0) H4(-2.6,0) H5(-1.95,0) H6(-1.3,0) H7(-0.65,0) H8(0,0) H9(0.65,0) H10(1.3,0) H11(1.95,0) H12(2.6,0) H13(3.25,0) H14(3.9,0) H15(4.55,0) J1(-4.55,-0.65) J2(-3.9,-0.65) J3(-3.25,-0.65) J4(-2.6,-0.65) J5(-1.95,-0.65) J6(-1.3,-0.65) J7(-0.65,-0.65) J8(0,-0.65) J9(0.65,-0.65) J10(1.3,-0.65) J11(1.95,-0.65) J12(2.6,-0.65) J13(3.25,-0.65) J14(3.9,-0.65) J15(4.55,-0.65) K1(-4.55,-1.3) K2(-3.9,-1.3) K3(-3.25,-1.3) K4(-2.6,-1.3) K5(-1.95,-1.3) K6(-1.3,-1.3) K7(-0.65,-1.3) K8(0,-1.3) K9(0.65,-1.3) K10(1.3,-1.3) K11(1.95,-1.3) K12(2.6,-1.3) K13(3.25,-1.3) K14(3.9,-1.3) K15(4.55,-1.3) L1(-4.55,-1.95) L2(-3.9,-1.95) L3(-3.25,-1.95) L4(-2.6,-1.95) L5(-1.95,-1.95) L6(-1.3,-1.95) L7(-0.65,-1.95) L8(0,-1.95) L9(0.65,-1.95) L10(1.3,-1.95) L11(1.95,-1.95) L12(2.6,-1.95) L13(3.25,-1.95) L14(3.9,-1.95) L15(4.55,-1.95) M1(-4.55,-2.6) M2(-3.9,-2.6) M3(-3.25,-2.6) M4(-2.6,-2.6) M5(-1.95,-2.6) M6(-1.3,-2.6) M7(-0.65,-2.6) M8(0,-2.6) M9(0.65,-2.6) M10(1.3,-2.6) M11(1.95,-2.6) M12(2.6,-2.6) M13(3.25,-2.6) M14(3.9,-2.6) M15(4.55,-2.6) N1(-4.55,-3.25) N2(-3.9,-3.25) N3(-3.25,-3.25) N4(-2.6,-3.25) N5(-1.95,-3.25) N6(-1.3,-3.25) N7(-0.65,-3.25) N8(0,-3.25) N9(0.65,-3.25) N10(1.3,-3.25) N11(1.95,-3.25) N12(2.6,-3.25) N13(3.25,-3.25) N14(3.9,-3.25) N15(4.55,-3.25) P1(-4.55,-3.9) P2(-3.9,-3.9) P3(-3.25,-3.9) P4(-2.6,-3.9) P5(-1.95,-3.9) P6(-1.3,-3.9) P7(-0.65,-3.9) P8(0,-3.9) P9(0.65,-3.9) P10(1.3,-3.9) P11(1.95,-3.9) P12(2.6,-3.9) P13(3.25,-3.9) P14(3.9,-3.9) P15(4.55,-3.9) R2(-3.9,-4.55) R3(-3.25,-4.55) R4(-2.6,-4.55) R5(-1.95,-4.55) R6(-1.3,-4.55) R7(-0.65,-4.55) R8(0,-4.55) R9(0.65,-4.55) R10(1.3,-4.55) R11(1.95,-4.55) R12(2.6,-4.55) R13(3.25,-4.55) R14(3.9,-4.55) R15(4.55,-4.55)
BOSCH_BMI323
  rect 0.675x0.25 smd: 1(-1.262,0.75) 2(-1.262,0.25) 3(-1.262,-0.25) 4(-1.262,-0.75) 8(1.262,-0.75) 9(1.262,-0.25) 10(1.262,0.25) 11(1.262,0.75)
  rect 0.25x0.675 smd: 5(-0.5,-1.012) 6(0,-1.012) 7(0.5,-1.012) 12(0.5,1.012) 13(0,1.012) 14(-0.5,1.012)
BOSCH_BMM350
  round 0.25 smd: A1(-0.4,0.4) A2(0,0.4) A3(0.4,0.4) B1(-0.4,0) B2(0,0) B3(0.4,0) C1(-0.4,-0.4) C2(0,-0.4) C3(0.4,-0.4)
CAPC0603_0201N
  rect 0.3x0.35 smd: 1(-0.275,0) 2(0.275,0)
CAPC1005_0402M
  rect 0.65x0.62 smd: 1(-0.49,0) 2(0.49,0)
CAPC1005_0402N
  rect 0.56x0.62 smd: 1(-0.48,0) 2(0.48,0)
CONV_XCL212B082DR
  rect 0.4x0.55 smd: 1(-1.5,2) 3(-1.5,0.65) 4(1.5,0.65) 6(1.5,2)
  rect 0.4x0.3 smd: 2(-1.5,1.325) 5(1.5,1.325)
  rect 0.55x0.4 smd: 7(0.8,2.3) 9(-0.8,2.3)
  custom 0.55x0.55 smd: 8(0,1.1)
  custom 0.312x0.312 smd: 10(-1,-1.2) 11(1,-1.2)
CONV_XCL240B183FR-G
  rect 0.35x0.375 smd: 1(-0.55,-0.938) 2(0,-0.938) 3(0.55,-0.938) 4(0.55,0.937) 5(0,0.937) 6(-0.55,0.937)
  rect 0.4x2.1 smd: 7(-1.25,0) 8(1.25,0)
  rect 1.5x1.1 smd: H(0,0)
DFN35P100X100X40-6N
  rect 0.55x0.2 smd: 1(-0.35,0.35) 2(-0.35,0) 3(-0.35,-0.35) 4(0.35,-0.35) 5(0.35,0) 6(0.35,0.35)
DFN65P100X100X43-5N
  custom 0.065x0.065 smd: 1(-0.325,-0.405) 2(0.325,-0.405) 3(0.325,0.405) 4(-0.325,0.405)
  rect 0.52x0.52 smd rot 45: 5(0,0)
GCT_USB4105-GF-A
  round 0.5 hole 0.65 unplated: (-2.89,2.605) (2.89,2.605)
  rect 0.3x1.15 smd: A1(-3.35,3.68) A4(-2.55,3.68) A5(-1.25,3.68) A6(-0.25,3.68) A7(0.25,3.68) A8(1.25,3.68) A9(2.55,3.68) A12(3.35,3.68) B1(3.05,3.68) B4(2.25,3.68) B5(1.75,3.68) B6(0.75,3.68) B7(-0.75,3.68) B8(-1.75,3.68) B9(-2.25,3.68) B12(-3.05,3.68)
  oval 1x2.1 hole 0.6x1.7: SH1(-4.32,3.105) SH2(4.32,3.105)
  oval 1x1.8 hole 0.6x1.4: SH3(-4.32,-1.075) SH4(4.32,-1.075)
HIROSE_DF40C-20DP-0P4V
  rect 0.23x0.66 smd: 1(-1.8,-1.355) 2(-1.8,1.355) 3(-1.4,-1.355) 4(-1.4,1.355) 5(-1,-1.355) 6(-1,1.355) 7(-0.6,-1.355) 8(-0.6,1.355) 9(-0.2,-1.355) 10(-0.2,1.355) 11(0.2,-1.355) 12(0.2,1.355) 13(0.6,-1.355) 14(0.6,1.355) 15(1,-1.355) 16(1,1.355) 17(1.4,-1.355) 18(1.4,1.355) 19(1.8,-1.355) 20(1.8,1.355)
  rect 0.35x0.66 smd: SH1(-2.275,-1.355) SH2(-2.275,1.355) SH3(2.275,-1.355) SH4(2.275,1.355)
ICT_TP_SMD_030RD_NSP
  round 0.75 smd: 1(0,0)
IND_74438336010
  rect 1.3x3.4 smd: 1(-1.05,0) 2(1.05,0)
IND_74479276222C
  rect 0.8x1.8 smd: 1(-0.8,0) 2(0.8,0)
INDC1005_0402M
  rect 0.7x0.72 smd: 1(-0.51,0) 2(0.51,0)
JST_S2B-PH-SM4-TB-LF-SN
  rect 1x3.5 smd: 1(1,-3.45) 2(-1,-3.45)
  rect 1.5x3.4 smd: SH1(3.35,2.3) SH2(-3.35,2.3)
JST_SM04B-SRSS-TB
  rect 0.6x1.55 smd: 1(-1.5,2.45) 2(-0.5,2.45) 3(0.5,2.45) 4(1.5,2.45)
  rect 1.2x1.8 smd: SH1(-2.8,-1.425) SH2(2.8,-1.425)
LED_150066M153000
  rect 0.8x0.5 smd: 1(-0.8,-0.45) 2(-0.8,0.45) 3(0.8,0.45) 4(0.8,-0.45)
LEDC1005X35N_AMB_WURTH
  rect 0.4x0.6 smd: A(0.5,0) K(-0.5,0)
LGA8S145X65P2X4_200X250X110
  rect 0.35x0.35 smd: 1(-0.975,0.725) 2(-0.325,0.725) 3(0.325,0.725) 4(0.975,0.725) 5(0.975,-0.725) 6(0.325,-0.725) 7(-0.325,-0.725) 8(-0.975,-0.725)
MIC_IM73A135V01XTSA1
  round 0.5 hole 0.8 unplated: (0,0.68)
  rect 0.75x0.45 smd: 1(-0.85,-1.5) 2(-0.85,-0.8) 3(0.85,-1.5) 4(0.85,-0.8)
  round 0.2 smd: 5(0,1.48)
MIC_IM73D122V01
  round 0.5 hole 0.8 unplated: (0,0.68)
  rect 0.75x0.45 smd: 1(-0.85,-1.5) 2(-0.85,-0.8) 3(0.85,-1.5) 4(0.85,-0.8)
  round 0.2 smd: 5(0,1.48)
MODULE_LBEE5HY2FY
  rect 0.25x0.5 smd: 1(-2.75,-3.1) 2(-2.25,-3.1) 3(-1.75,-3.1) 4(-1.25,-3.1) 5(-0.75,-3.1) 6(-0.25,-3.1) 7(0.25,-3.1) 8(0.75,-3.1) 9(1.25,-3.1) 10(1.75,-3.1) 11(2.25,-3.1) 12(2.75,-3.1) 27(2.75,3.1) 28(2.25,3.1) 29(1.75,3.1) 30(1.25,3.1) 31(0.75,3.1) 32(0.25,3.1) 33(-0.25,3.1) 34(-0.75,3.1) 35(-1.25,3.1) 36(-1.75,3.1) 37(-2.25,3.1) 38(-2.75,3.1) 54(-0.75,-1.95) 55(-0.25,-1.95) 56(0.25,-1.95) 57(0.75,-1.95) 62(0.75,1.95) 63(0.25,1.95) 64(-0.25,1.95) 65(-0.75,1.95)
  rect 0.5x0.25 smd: 13(3.4,-3.25) 14(3.4,-2.75) 15(3.4,-2.25) 16(3.4,-1.75) 17(3.4,-1.25) 18(3.4,-0.75) 19(3.4,-0.25) 20(3.4,0.25) 21(3.4,0.75) 22(3.4,1.25) 23(3.4,1.75) 24(3.4,2.25) 25(3.4,2.75) 26(3.4,3.25) 39(-3.4,3.25) 40(-3.4,2.75) 41(-3.4,2.25) 42(-3.4,1.75) 43(-3.4,1.25) 44(-3.4,0.75) 45(-3.4,0.25) 46(-3.4,-0.25) 47(-3.4,-0.75) 48(-3.4,-1.25) 49(-3.4,-1.75) 50(-3.4,-2.25) 51(-3.4,-2.75) 52(-3.4,-3.25)
  rect 1x1 smd: 53(-1.95,-1.95) 58(1.95,-1.95) 59(1.95,-0.65) 60(1.95,0.65) 61(1.95,1.95) 66(-1.95,1.95) 67(-1.95,0.65) 68(-1.95,-0.65) 69(-0.65,-0.65) 70(0.65,-0.65) 71(0.65,0.65) 72(-0.65,0.65)
MOLEX_532610271
  rect 0.8x1.6 smd: 1(0,0) 2(-1.25,0)
  rect 2.1x3 smd: SH1(2.55,2.9) SH2(-3.8,2.9)
OSCCC200X160X80-4N
  rect 0.6x0.8 smd: 1(-0.9,-0.6) 2(0.9,-0.6) 3(0.9,0.6) 4(-0.9,0.6)
OSCCC200X250X90-4N
  rect 0.9x0.8 smd: 1(-0.925,-0.725) 2(0.925,-0.725) 3(0.925,0.725) 4(-0.925,0.725)
OSCS4_SIT_2M0X1M2SPL_NGOPQ
  rect 0.5x0.2 smd: G(-0.45,0.1) P(0.45,-0.1)
  rect 1.4x0.4 smd: N(0,0.8) O(0,-0.8)
QFN40P800X800_68-H580N
  rect 0.8x0.2 smd: 1(-3.95,3.2) 2(-3.95,2.8) 3(-3.95,2.4) 4(-3.95,2) 5(-3.95,1.6) 6(-3.95,1.2) 7(-3.95,0.8) 8(-3.95,0.4) 9(-3.95,0) 10(-3.95,-0.4) 11(-3.95,-0.8) 12(-3.95,-1.2) 13(-3.95,-1.6) 14(-3.95,-2) 15(-3.95,-2.4) 16(-3.95,-2.8) 17(-3.95,-3.2) 35(3.95,-3.2) 36(3.95,-2.8) 37(3.95,-2.4) 38(3.95,-2) 39(3.95,-1.6) 40(3.95,-1.2) 41(3.95,-0.8) 42(3.95,-0.4) 43(3.95,0) 44(3.95,0.4) 45(3.95,0.8) 46(3.95,1.2) 47(3.95,1.6) 48(3.95,2) 49(3.95,2.4) 50(3.95,2.8) 51(3.95,3.2)
  rect 0.2x0.8 smd: 18(-3.2,-3.95) 19(-2.8,-3.95) 20(-2.4,-3.95) 21(-2,-3.95) 22(-1.6,-3.95) 23(-1.2,-3.95) 24(-0.8,-3.95) 25(-0.4,-3.95) 26(0,-3.95) 27(0.4,-3.95) 28(0.8,-3.95) 29(1.2,-3.95) 30(1.6,-3.95) 31(2,-3.95) 32(2.4,-3.95) 33(2.8,-3.95) 34(3.2,-3.95) 52(3.2,3.95) 53(2.8,3.95) 54(2.4,3.95) 55(2,3.95) 56(1.6,3.95) 57(1.2,3.95) 58(0.8,3.95) 59(0.4,3.95) 60(0,3.95) 61(-0.4,3.95) 62(-0.8,3.95) 63(-1.2,3.95) 64(-1.6,3.95) 65(-2,3.95) 66(-2.4,3.95) 67(-2.8,3.95) 68(-3.2,3.95)
  rect 5.8x5.8 smd: H(0,0)
QFN50P500X500X100-32N_TP_NOFID
  rrect 0.6x0.25 smd: 1(-2.4,1.75) 2(-2.4,1.25) 3(-2.4,0.75) 4(-2.4,0.25) 5(-2.4,-0.25) 6(-2.4,-0.75) 7(-2.4,-1.25) 8(-2.4,-1.75) 17(2.4,-1.75) 18(2.4,-1.25) 19(2.4,-0.75) 20(2.4,-0.25) 21(2.4,0.25) 22(2.4,0.75) 23(2.4,1.25) 24(2.4,1.75)
  rrect 0.25x0.6 smd: 9(-1.75,-2.4) 10(-1.25,-2.4) 11(-0.75,-2.4) 12(-0.25,-2.4) 13(0.25,-2.4) 14(0.75,-2.4) 15(1.25,-2.4) 16(1.75,-2.4) 25(1.75,2.4) 26(1.25,2.4) 27(0.75,2.4) 28(0.25,2.4) 29(-0.25,2.4) 30(-0.75,2.4) 31(-1.25,2.4) 32(-1.75,2.4)
  rrect 3.45x3.45 smd: H(0,0)
RESC0603_0201N
  rect 0.25x0.35 smd: 1(-0.3,0) 2(0.3,0)
RESC1005_0402N
  rect 0.4x0.55 smd: 1(-0.425,0) 2(0.425,0)
RESC1608_0603M
  rect 1x1 smd: 1(-0.9,0) 2(0.9,0)
RESC1608_0603N
  rect 0.9x1 smd: 1(-0.75,0) 2(0.75,0)
RTST254P2X10_W515
  rect 1.55x1.55 hole 1.05: 1(0,0)
  round 1.55 hole 1.05: 2(0,-2.54) 3(2.54,0) 4(2.54,-2.54) 5(5.08,0) 6(5.08,-2.54) 7(7.62,0) 8(7.62,-2.54) 9(10.16,0) 10(10.16,-2.54) 11(12.7,0) 12(12.7,-2.54) 13(15.24,0) 14(15.24,-2.54) 15(17.78,0) 16(17.78,-2.54) 17(20.32,0) 18(20.32,-2.54) 19(22.86,0) 20(22.86,-2.54)
SAMT_FTSH-105-XX-X-DV-K
  rect 0.75x2.8 smd: 1(-2.54,-2.03) 2(-2.54,2.03) 3(-1.27,-2.03) 4(-1.27,2.03) 5(0,-2.03) 6(0,2.03) 7(1.27,-2.03) 8(1.27,2.03) 9(2.54,-2.03) 10(2.54,2.03)
SAMTEC_TSM-102-01-L-DH-A-P-TR
  round 2.48 hole 1.78: (0,0)
  rect 1.27x3.18 smd: 1(-1.27,4.305) 2(-1.27,8.495) 3(1.27,4.305) 4(1.27,8.495)
SENSOR_SHT40-AD1B-R2
  rect 0.5x0.3 smd: 1(-0.7,0.4) 2(-0.7,-0.4) 3(0.7,-0.4) 4(0.7,0.4)
SODFL1608X77N
  rect 0.6x0.8 smd: A(-0.85,0) K(0.85,0)
SON50P100X200_08_SOT833-1
  rect 0.35x0.25 smd: 1(-0.275,0.75)
  rect 0.3x0.25 smd: 2(-0.3,0.25) 3(-0.3,-0.25) 4(-0.3,-0.75) 5(0.3,-0.75) 6(0.3,-0.25) 7(0.3,0.25) 8(0.3,0.75)
SON50P200X180X60-6N_TP
  rect 0.45x0.35 smd: 1(-0.975,0.55)
  rect 0.45x0.25 smd: 2(-0.975,0) 3(-0.975,-0.5) 4(0.975,-0.5) 5(0.975,0) 6(0.975,0.5)
  custom 0.25x0.25 smd: H(0,0)
SOT65P210X100-6M
  rect 1.1x0.45 smd: 1(-1.15,0.65) 2(-1.15,0) 3(-1.15,-0.65) 4(1.15,-0.65) 5(1.15,0) 6(1.15,0.65)
SOTFL40P120X50-3N_MOSFET_TOREX
  rect 0.42x0.3 smd: D(0,0.5)
  rect 0.32x0.3 smd: G(-0.4,-0.5) S(0.4,-0.5)
SOTFL40P120X59-3N
  rect 0.45x0.4 smd: 1(-0.525,0.4) 2(-0.525,-0.4) 3(0.525,0)
SULLINS_PRPC006SFAN-RC
  rect 1.6x1.6 hole 1: 1(0,0)
  round 1.6 hole 1: 2(2.54,0) 3(5.08,0) 4(7.62,0) 5(10.16,0) 6(12.7,0)
SW_434133025816
  rect 1.05x0.65 smd: 1(-2.075,1.075) 2(2.075,1.075) 3(-2.075,-1.075) 4(2.075,-1.075)
SW_SKRPACE010
  rect 1.05x0.65 smd: 1(-2.075,1.075) 2(2.075,1.075) 3(-2.075,-1.075) 4(2.075,-1.075)
unnamed#2
  round 1 hole 3 unplated: (0,0)
VF2BGA40N50P9X12_500X650X90
  round 0.275 smd: A1(-2.17,2.58) A2(-1.67,2.58) A3(-1.17,2.58) A4(-0.67,2.58) A5(-0.17,2.58) A6(0.33,2.58) A7(0.83,2.58) A8(1.33,2.58) A9(1.83,2.58) B1(-2.17,2.08) B3(-1.17,2.08) B4(-0.67,2.08) B8(1.33,2.08) B9(1.83,2.08) C1(-2.17,1.58) C9(1.83,1.58) D1(-2.17,1.08) D9(1.83,1.08) E1(-2.17,0.58) E9(1.83,0.58) F1(-2.17,0.08) F9(1.83,0.08) G1(-2.17,-0.42) G9(1.83,-0.42) H1(-2.17,-0.92) H9(1.83,-0.92) J1(-2.17,-1.42) J9(1.83,-1.42) K1(-2.17,-1.92) K9(1.83,-1.92) L1(-2.17,-2.42) L9(1.83,-2.42) M1(-2.17,-2.92) M2(-1.67,-2.92) M3(-1.17,-2.92) M4(-0.67,-2.92) M5(-0.17,-2.92) M6(0.33,-2.92) M7(0.83,-2.92) M9(1.83,-2.92)
VQFN50P200X200X100-7N_TI
  rrect 1.15x0.35 smd: 1(-0.625,0.55) 3(-0.625,-0.55)
  rrect 1.45x0.2 smd: 2(-0.475,0)
  rrect 0.45x0.25 smd: 4(0.975,-0.75) 5(0.975,-0.25) 6(0.975,0.25) 7(0.975,0.75)
X2QFN40P160X160X40-12N_TI
  rrect 0.7x0.2 smd: 1(-0.65,0.2) 2(-0.65,-0.2) 7(0.65,-0.2) 8(0.65,0.2)
  rrect 0.2x0.5 smd: 3(-0.6,-0.75) 4(-0.2,-0.75) 5(0.2,-0.75) 6(0.6,-0.75) 9(0.6,0.75) 10(0.2,0.75) 11(-0.2,0.75) 12(-0.6,0.75)
XFDFN50P180X150X33-7N_TOREX
  rect 0.36x0.3 smd: 1(-0.82,0.5) 2(-0.82,0) 3(-0.82,-0.5) 4(0.82,-0.5) 5(0.82,0) 6(0.82,0.5)
  rect 0.84x1.3 smd: H(0,0)
XTAL_ABS05_1M6X1M
  rect 0.5x1 smd: 1(-0.6,0) 2(0.6,0)
XTALS4_2MX1M6
  rect 0.7x0.8 smd: 1(-0.5,0.65) 2(-0.5,-0.65) 3(0.5,-0.65) 4(0.5,0.65)

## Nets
